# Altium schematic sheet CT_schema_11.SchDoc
size 385 x 385 mm
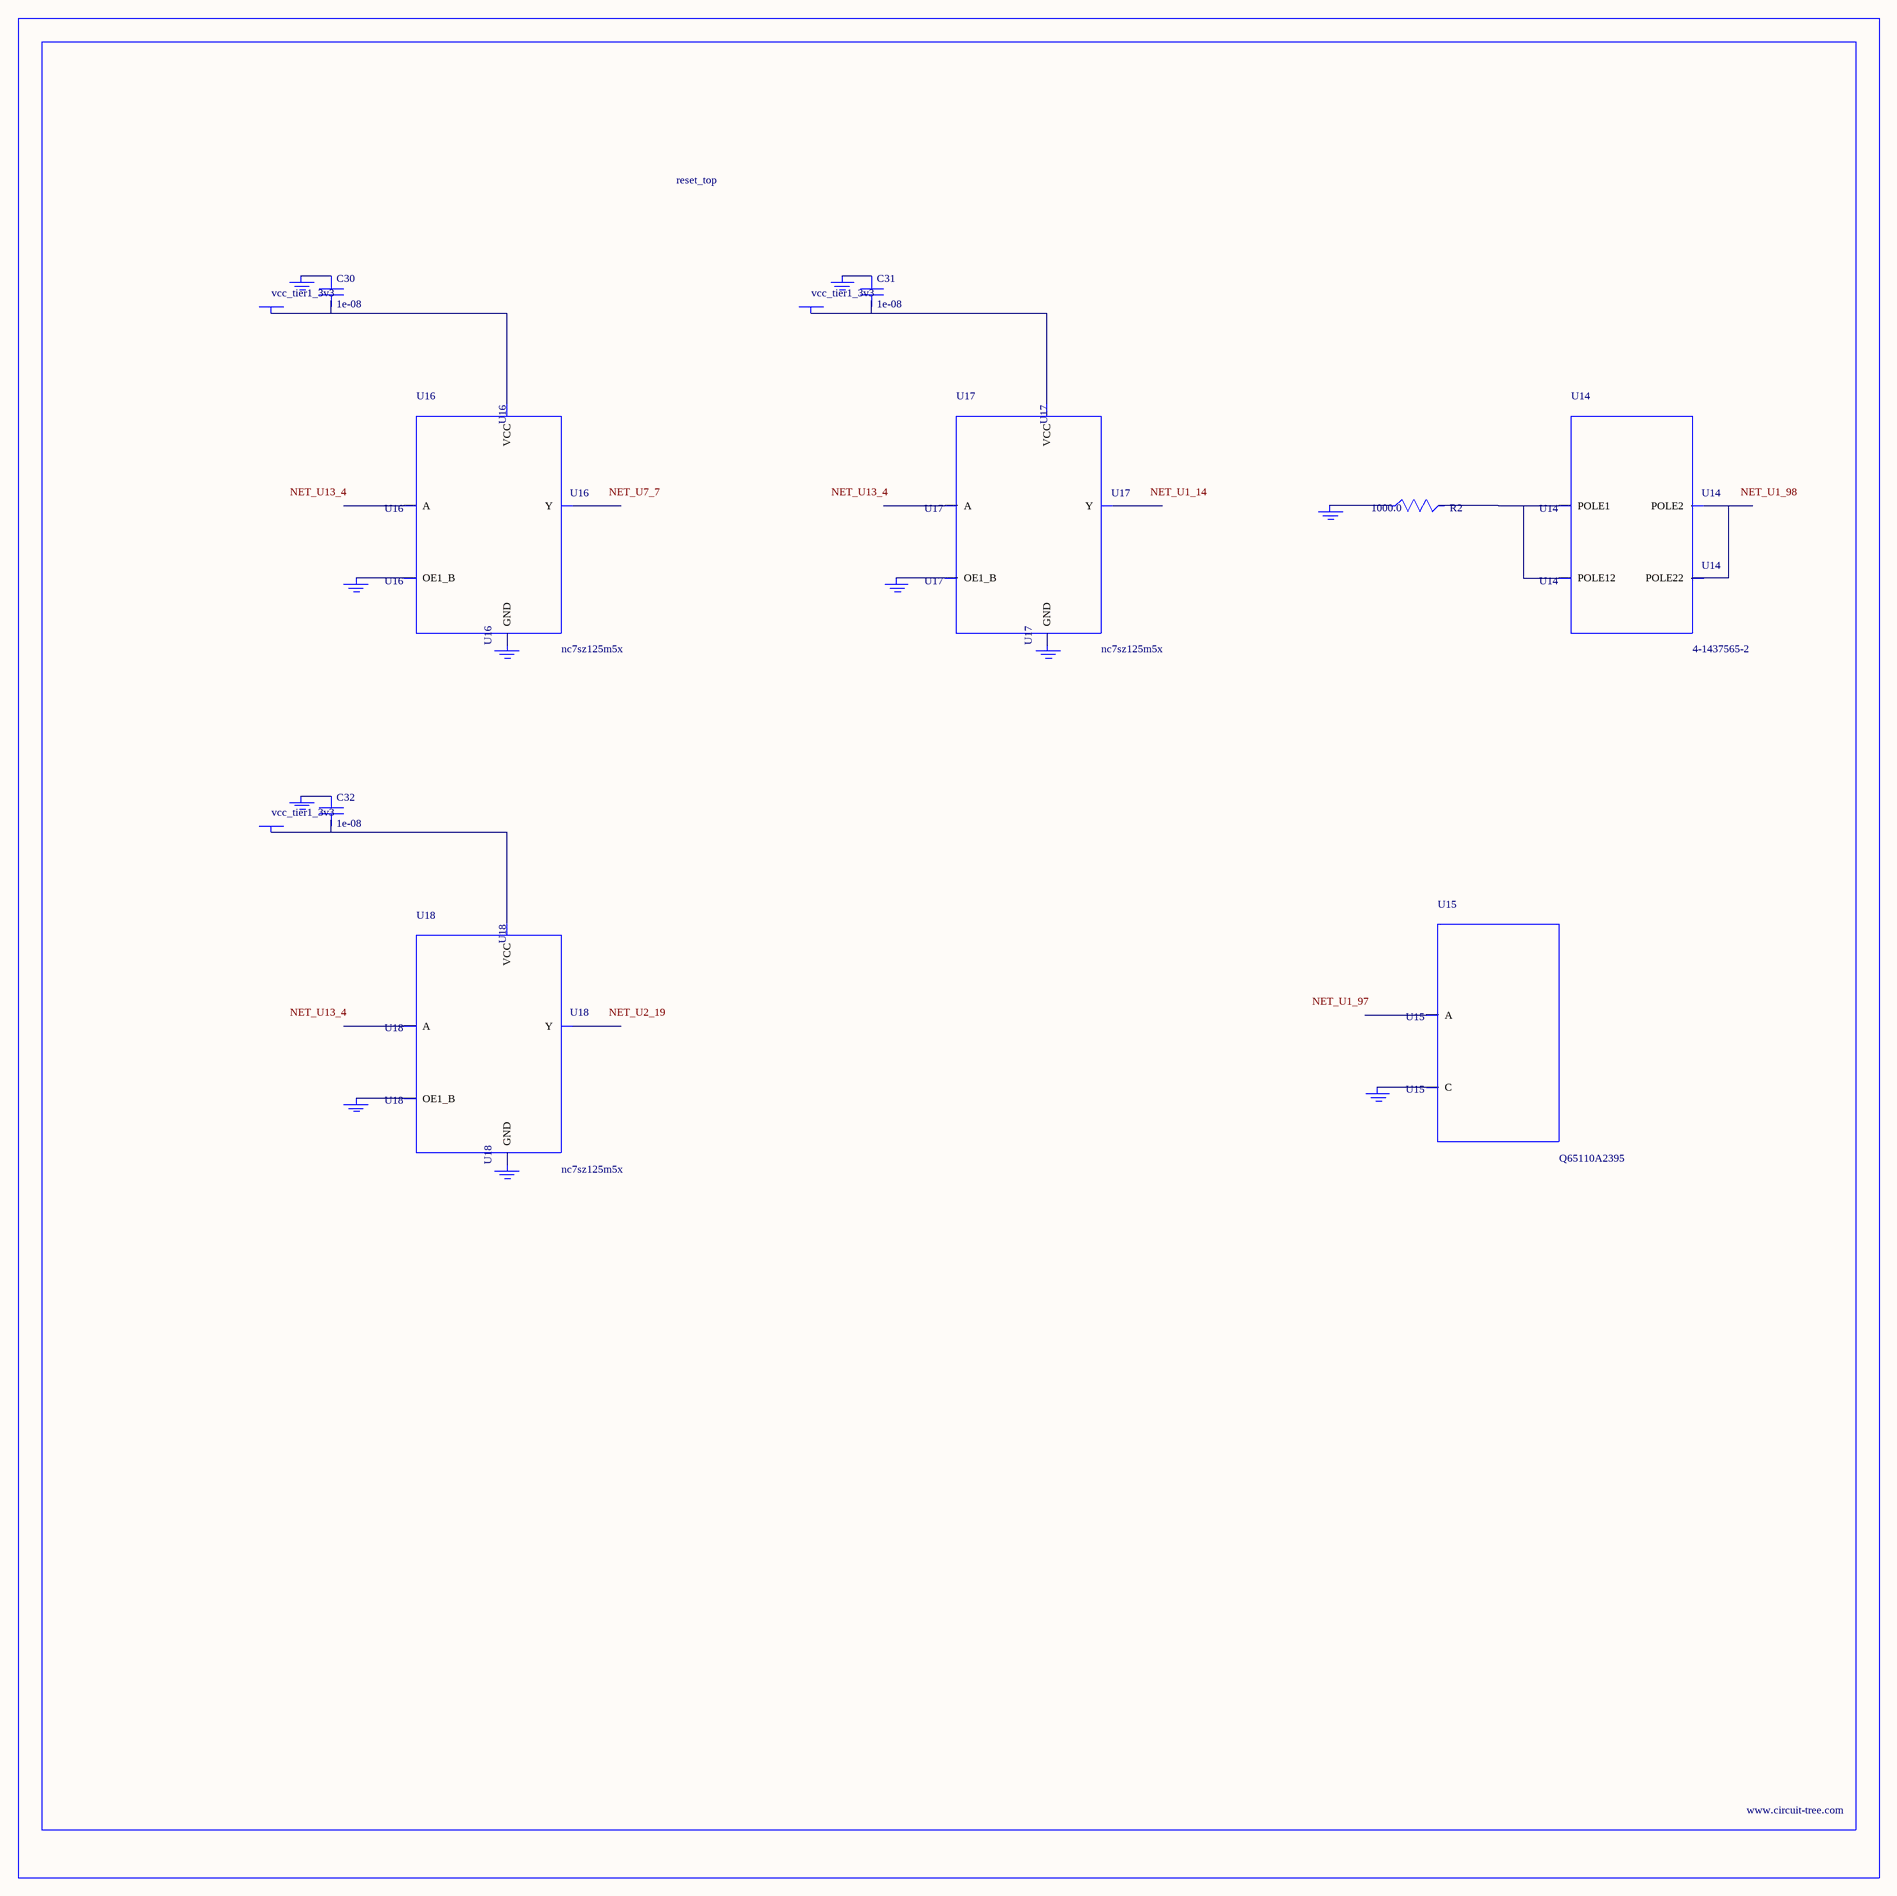
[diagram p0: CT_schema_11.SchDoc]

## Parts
BORDER10  (no value)
C30  1e-08  [C0402]
C31  1e-08  [C0402]
C32  1e-08  [C0402]
GND_INSTANCE_10_0  (no value)
GND_INSTANCE_10_1  (no value)
GND_INSTANCE_10_2  (no value)
GND_INSTANCE_10_3  (no value)
GND_INSTANCE_10_4  (no value)
GND_INSTANCE_10_5  (no value)
GND_INSTANCE_10_6  (no value)
GND_INSTANCE_10_7  (no value)
GND_INSTANCE_10_8  (no value)
GND_INSTANCE_10_9  (no value)
GND_INSTANCE_10_10  (no value)
POWER_INSTANCE_10_0  vcc_tier1_3v3
POWER_INSTANCE_10_1  vcc_tier1_3v3
POWER_INSTANCE_10_2  vcc_tier1_3v3
R2  1000.0  [R0603]
U14  4-1437565-2  [SW_4-1437565-2]
U15  Q65110A2395  [LGM67K-G1J2-24-Z]
U16  nc7sz125m5x  [NC7SZ125M5X]
U17  nc7sz125m5x  [NC7SZ125M5X]
U18  nc7sz125m5x  [NC7SZ125M5X]

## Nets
NetC30_1: C30.1 GND_INSTANCE_10_2.0(GND)
NetC30_2: C30.2 POWER_INSTANCE_10_0.0(PWR) U16.5(VCC)
NetC31_1: C31.1 GND_INSTANCE_10_5.0(GND)
NetC31_2: C31.2 POWER_INSTANCE_10_1.0(PWR) U17.5(VCC)
NetC32_1: C32.1 GND_INSTANCE_10_8.0(GND)
NetC32_2: C32.2 POWER_INSTANCE_10_2.0(PWR) U18.5(VCC)
NetGND_INSTANCE_10_0_0: GND_INSTANCE_10_0.0(GND) R2.1
NetGND_INSTANCE_10_1_0: GND_INSTANCE_10_1.0(GND) U15.C
NetGND_INSTANCE_10_3_0: GND_INSTANCE_10_3.0(GND) U16.1(OE1_B)
NetGND_INSTANCE_10_4_0: GND_INSTANCE_10_4.0(GND) U16.3(GND)
NetGND_INSTANCE_10_6_0: GND_INSTANCE_10_6.0(GND) U17.1(OE1_B)
NetGND_INSTANCE_10_7_0: GND_INSTANCE_10_7.0(GND) U17.3(GND)
NetGND_INSTANCE_10_9_0: GND_INSTANCE_10_9.0(GND) U18.1(OE1_B)
NetGND_INSTANCE_10_10_0: GND_INSTANCE_10_10.0(GND) U18.3(GND)
NetR2_2: R2.2 U14.1(POLE1) U14.2(POLE12)
NetU14_3: U14.3(POLE2) U14.4(POLE22)

Not connected (* = marked no-connect by the designer): U15 A; U16 2(A) 4(Y); U17 2(A) 4(Y); U18 2(A) 4(Y)

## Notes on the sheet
- Labels drawn without touching a wire or pin: NET_U1_14, NET_U1_97, NET_U1_98, NET_U2_19, NET_U7_7, NET_U13_4

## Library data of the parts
BORDER10 = BORDER_PAGE10
C30-C32 = C0402C103K3RAC
GND_INSTANCE_10_0-GND_INSTANCE_10_10 = GND
POWER_INSTANCE_10_0-POWER_INSTANCE_10_2 = PWR
R2 = RC0603JR-071KL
